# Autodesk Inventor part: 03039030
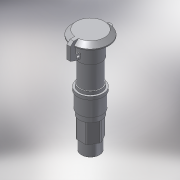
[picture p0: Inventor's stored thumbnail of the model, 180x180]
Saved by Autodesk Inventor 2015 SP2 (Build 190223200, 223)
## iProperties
Created: 2017-06
Part Number: 03039030
Material: PVC-Piping
Description: PLASSON QUICK COUPLING VALVE 1"
Document SubType Name: Modeling
Designer: KIM
Mass: 262.982 g
Surface Area: 296.369 cm^2
Volume: 187.844 cm^3
Density: 1.4 g/cm^3
Appearance: Smooth - White
Author: KIM
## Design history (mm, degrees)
derived "03039.ipt"
feature "Solid1::03039.ipt"
tag "TaggingFeature1"
body "Solid1"
other parameters: "d1" = 154, "d23" = 18, "d24" = 46.2, "d25" = 53.9, "d26" = 77, "d27" = 81.62, "d28" = 86.24, "d29" = 120.12, "d32" = 146.3, "d33" = 147.84, "d34" = 33.249, "d40" = 36, "d45" = 39.8988, "d46" = 43.2237, "d47" = 46.5486, "d49" = 36.5739, "d54" = 39.8988, "d55" = 66.498, "d65" = 45 deg, "d66" = 26.5992, "d69" = 0, "d70" = 1.66245, "d73" = 0.66498, "d76" = 9.9747, "d77" = 26.5992, "d78" = 135 deg, "d79" = 110 deg, "d80" = 110 deg, "d81" = 9.9747, "d82" = 3.3249, "d83" = 23.1, "d84" = 6.6498, "d85" = 0, "d86" = 4.98735, "d87" = 13.2996, "d88" = 0, "d89" = 3.3249, "d90" = 3.3249, "d91" = 0, "d92" = 9.9747, "d93" = 1.99494, "d94" = 11.96964, "d95" = 1.66245, "d96" = 0, "R_" = 33.249, "H_" = 154, "l_2" = 18, "d48" = 39.8988
